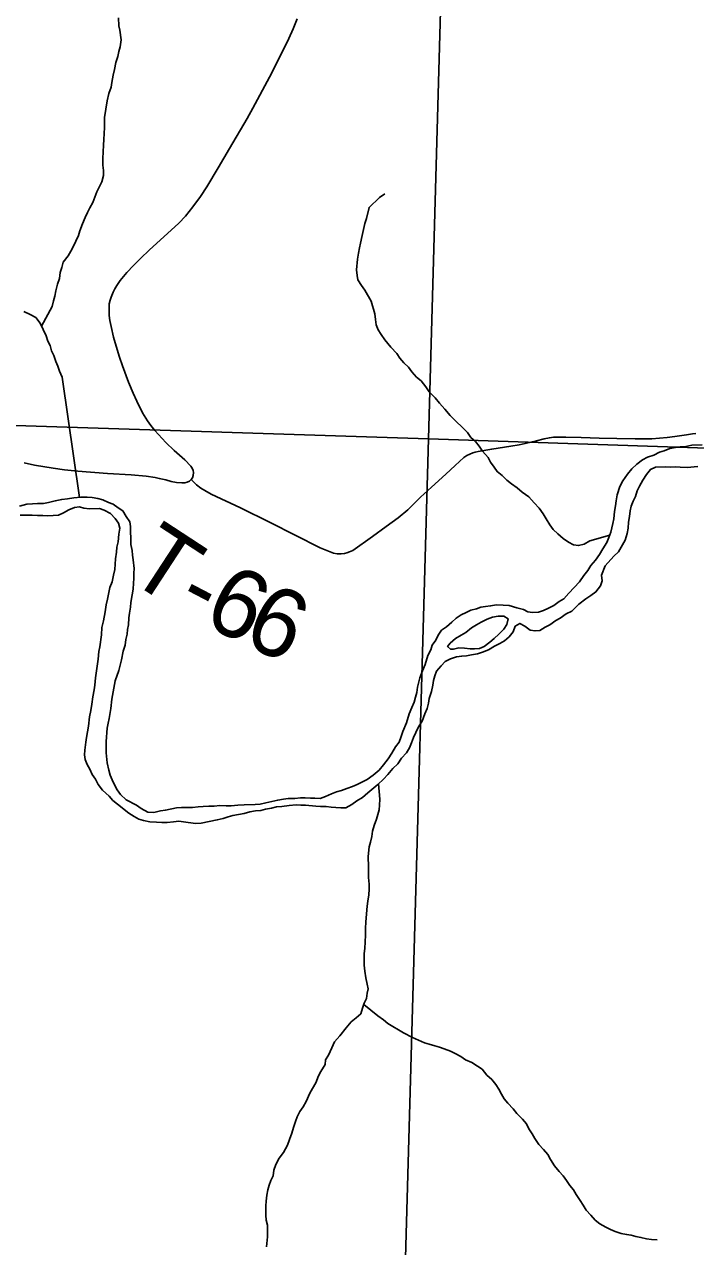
# Model space of a CAD drawing. Extents: x -7.9 to 76.1, y 0 to 22.
# Drawn here: x 7.895 to 8.447, y 14.511 to 15.518 of the extents above; entities that cross this region are included whole.
import ezdxf

# ---------------------------------------------------------------- set-up
doc = ezdxf.new("R2010")
doc.units = 0
for name, color, linetype in [('GM_X_Major_River', 7, 'Continuous'), ('GM_X_Minor_River', 7, 'Continuous'), ('GM_X_Section', 7, 'Continuous'), ('GM_X_State_Route', 7, 'Continuous'), ('GM_X_Township_Road', 7, 'Continuous'), ('GM_X_Township_Road_Text', 7, 'Continuous'), ('SC_Scratch1', 7, 'Continuous')]:
    doc.layers.add(name, color=color, linetype=linetype)

msp = doc.modelspace()

# ---------------------------------------------------------------- linework, layer by layer
at = {"layer": 'GM_X_Major_River'}
for points in [[(8.2669, 15.0364), (8.2707, 15.0376), (8.2745, 15.0384), (8.2786, 15.0388), (8.2835, 15.0397), (8.2889, 15.0393), (8.2938, 15.039), (8.3003, 15.0372), (8.3056, 15.0358), (8.3094, 15.0339), (8.3132, 15.0332), (8.3181, 15.0337), (8.3223, 15.0349), (8.3264, 15.0368), (8.3306, 15.0392), (8.3351, 15.0423), (8.3388, 15.0446), (8.3429, 15.0492), (8.3519, 15.0585), (8.3553, 15.0638), (8.3586, 15.068), (8.3612, 15.0719), (8.3649, 15.0765), (8.3683, 15.0811), (8.3709, 15.0857), (8.3742, 15.091), (8.3761, 15.0952), (8.3775, 15.0994), (8.3793, 15.1067), (8.38, 15.1105), (8.3807, 15.1165), (8.3814, 15.1211), (8.3821, 15.1253), (8.3828, 15.1302), (8.385, 15.1371), (8.3876, 15.1417), (8.3913, 15.1471), (8.395, 15.1517), (8.3991, 15.1555), (8.4037, 15.159), (8.4078, 15.1613), (8.4131, 15.1629), (8.4176, 15.1653), (8.4214, 15.1665), (8.4263, 15.1684), (8.4308, 15.1692), (8.4346, 15.1697), (8.4395, 15.1701), (8.4444, 15.171), (8.4528, 15.1715)], [(8.2317, 14.9774), (8.2328, 14.9813), (8.2342, 14.9851), (8.238, 14.9893), (8.2413, 14.9931), (8.2455, 14.9951), (8.2504, 14.9967), (8.2549, 14.9975), (8.2587, 14.9976), (8.2629, 14.9984), (8.2678, 14.9992), (8.2719, 15.0008), (8.2768, 15.0027), (8.2817, 15.0055), (8.2862, 15.0078), (8.29, 15.0101), (8.2938, 15.0132), (8.2971, 15.0175), (8.2989, 15.022), (8.3027, 15.0244), (8.3069, 15.0221), (8.3111, 15.0188), (8.3153, 15.0181), (8.3191, 15.0185), (8.3236, 15.0212), (8.3274, 15.0232), (8.3323, 15.0267), (8.336, 15.0286), (8.3409, 15.0321), (8.3454, 15.0345), (8.3514, 15.0402), (8.357, 15.0445), (8.3612, 15.0472), (8.3653, 15.0503), (8.369, 15.0553), (8.3705, 15.0595), (8.37, 15.064), (8.373, 15.0717), (8.3801, 15.0797), (8.3838, 15.0832), (8.3894, 15.0928), (8.3912, 15.0985), (8.3919, 15.1027), (8.3922, 15.1076), (8.3929, 15.1125), (8.3936, 15.1171), (8.3943, 15.1209), (8.3961, 15.1251), (8.398, 15.1289), (8.3994, 15.1335), (8.4013, 15.1373), (8.4039, 15.1423), (8.4069, 15.1469), (8.4102, 15.1511), (8.4144, 15.1531), (8.4223, 15.1532), (8.4269, 15.1529), (8.431, 15.1533), (8.4348, 15.153), (8.4405, 15.1527), (8.4492, 15.1536)], [(7.8907, 15.121), (7.8968, 15.1226), (7.9013, 15.1227), (7.9055, 15.1231), (7.9104, 15.1232), (7.9146, 15.124), (7.9202, 15.1252), (7.9255, 15.1265), (7.9301, 15.1269), (7.9354, 15.1277), (7.9411, 15.1282), (7.9464, 15.1283), (7.9505, 15.1279), (7.9551, 15.1273), (7.9593, 15.1262), (7.9639, 15.124), (7.9677, 15.1225), (7.9719, 15.1195), (7.9757, 15.1169), (7.9784, 15.1124), (7.9815, 15.1079), (7.982, 15.1041), (7.982, 15.0992), (7.9825, 15.095), (7.9825, 15.0893), (7.9834, 15.0844), (7.9838, 15.0806), (7.9842, 15.0768), (7.9851, 15.0696), (7.9848, 15.0658), (7.9848, 15.0613), (7.9845, 15.0575), (7.9842, 15.0525)], [(7.8912, 15.1135), (7.8965, 15.1135), (7.9011, 15.1136), (7.9056, 15.1133), (7.9098, 15.1133), (7.914, 15.113), (7.9185, 15.1131), (7.9227, 15.1135), (7.9268, 15.1155), (7.9313, 15.1178), (7.9359, 15.1198), (7.94, 15.1202), (7.9438, 15.1191), (7.9484, 15.1188), (7.9567, 15.1189), (7.9605, 15.1175), (7.9655, 15.1149), (7.9694, 15.1108), (7.9721, 15.107), (7.9733, 15.1028), (7.9726, 15.0979), (7.9719, 15.0914)], [(7.9719, 15.0914), (7.9708, 15.0872), (7.9705, 15.0831), (7.9698, 15.0774), (7.9692, 15.0686), (7.9681, 15.0641), (7.967, 15.0587), (7.9652, 15.0538), (7.9641, 15.0484), (7.9631, 15.0443), (7.962, 15.0397), (7.9613, 15.034), (7.9599, 15.0264), (7.9584, 15.021), (7.9581, 15.015), (7.9568, 15.0051), (7.956, 15.0013), (7.9554, 14.9948), (7.9533, 14.9796), (7.9526, 14.9735), (7.9523, 14.9697), (7.9512, 14.964), (7.9502, 14.9579), (7.9495, 14.9526), (7.9484, 14.9473), (7.9474, 14.9397), (7.946, 14.9305), (7.9453, 14.9267), (7.9446, 14.9199), (7.9443, 14.9161), (7.9447, 14.9123), (7.9463, 14.9082), (7.9486, 14.9044), (7.9506, 14.8999), (7.9533, 14.8961), (7.9556, 14.8916), (7.9591, 14.8871), (7.9645, 14.8822), (7.9676, 14.8785), (7.9714, 14.8755), (7.9806, 14.868), (7.9852, 14.8654), (7.989, 14.8632), (7.9928, 14.8621), (7.9981, 14.8611), (8.0034, 14.8608), (8.008, 14.8605), (8.0122, 14.8605), (8.0175, 14.861), (8.022, 14.8614), (8.0258, 14.8611), (8.0357, 14.8597), (8.0402, 14.8598), (8.0535, 14.8626), (8.0584, 14.8638), (8.0625, 14.865), (8.0663, 14.8662), (8.0709, 14.867), (8.0758, 14.8679), (8.0803, 14.8691), (8.0849, 14.8699), (8.0894, 14.8703), (8.0932, 14.8715), (8.0981, 14.8723), (8.1022, 14.8732), (8.1068, 14.8736), (8.1128, 14.8744), (8.1185, 14.8749), (8.1223, 14.8746), (8.1261, 14.8746), (8.1348, 14.874), (8.1386, 14.8737), (8.1432, 14.8737), (8.1474, 14.873), (8.1512, 14.8727), (8.1553, 14.8724), (8.1595, 14.8724), (8.1644, 14.8752), (8.1685, 14.8783), (8.1731, 14.881), (8.1776, 14.8848), (8.1858, 14.8918), (8.1903, 14.896), (8.194, 14.8999), (8.1981, 14.9049), (8.2023, 14.9087), (8.2052, 14.9133), (8.2093, 14.9179), (8.2119, 14.9218), (8.2134, 14.926), (8.2152, 14.9305), (8.2171, 14.9344), (8.2193, 14.9393), (8.2223, 14.9439), (8.2245, 14.95), (8.2263, 14.9542), (8.2274, 14.9588), (8.2281, 14.9626), (8.2299, 14.9683), (8.231, 14.9736), (8.2317, 14.9774)], [(7.9842, 15.0525), (7.9835, 15.048), (7.9824, 15.0415), (7.9821, 15.0377), (7.9814, 15.0327), (7.9807, 15.0289), (7.9804, 15.0232), (7.9797, 15.0194), (7.9794, 15.0156), (7.9783, 15.0111), (7.9776, 15.0065), (7.9761, 15.0016), (7.9747, 14.9943), (7.9726, 14.9856), (7.9696, 14.9772), (7.9668, 14.962), (7.9658, 14.9544), (7.9644, 14.946), (7.9637, 14.9422), (7.963, 14.938), (7.962, 14.927), (7.962, 14.9232), (7.9621, 14.9179), (7.963, 14.9095), (7.9642, 14.9035), (7.9654, 14.8993), (7.967, 14.8955), (7.9689, 14.8914), (7.9712, 14.8873), (7.9739, 14.8835), (7.9786, 14.879), (7.987, 14.8746), (7.9908, 14.872), (7.9965, 14.869), (8.0014, 14.8687), (8.0067, 14.8699), (8.0109, 14.8707), (8.02, 14.8724), (8.0241, 14.8728), (8.0332, 14.8729), (8.0378, 14.8734), (8.042, 14.8735), (8.0465, 14.8739), (8.051, 14.874), (8.0556, 14.8744), (8.0609, 14.8741), (8.0651, 14.8742), (8.0704, 14.8746), (8.0757, 14.8751), (8.0848, 14.8752), (8.0889, 14.8756), (8.0935, 14.8765), (8.1033, 14.8789), (8.1082, 14.8797), (8.112, 14.8801), (8.1173, 14.8802), (8.1222, 14.8807), (8.126, 14.8807), (8.1302, 14.8804), (8.134, 14.8804), (8.1382, 14.8801), (8.1427, 14.8817), (8.1476, 14.884), (8.1518, 14.8856), (8.1559, 14.8868), (8.1601, 14.8884), (8.165, 14.89), (8.1687, 14.8916), (8.177, 14.8958), (8.1819, 14.8993), (8.1868, 14.9036), (8.1905, 14.9078), (8.1942, 14.9128), (8.1972, 14.9174), (8.2002, 14.9227), (8.2032, 14.9266), (8.205, 14.9311), (8.2064, 14.9353), (8.2094, 14.9426), (8.2116, 14.9498), (8.2138, 14.9552), (8.2156, 14.9594), (8.2167, 14.9636), (8.2178, 14.9674), (8.2185, 14.9719), (8.2203, 14.9796), (8.2225, 14.9853), (8.2247, 14.9906), (8.2268, 14.9979), (8.2294, 15.0025), (8.2305, 15.0063), (8.2335, 15.0105), (8.2353, 15.0147), (8.2383, 15.0189), (8.2424, 15.0216), (8.2466, 15.0255), (8.2503, 15.0286), (8.2545, 15.0313), (8.2586, 15.0332), (8.2624, 15.0352), (8.2669, 15.0364)], [(8.2457, 15.0032), (8.2432, 15.0052), (8.2453, 15.008), (8.2498, 15.0119), (8.2543, 15.0146), (8.2581, 15.0169), (8.2629, 15.0208), (8.2671, 15.0231), (8.2708, 15.0254), (8.2757, 15.0278), (8.2803, 15.0294), (8.2848, 15.0302), (8.2894, 15.0302), (8.2932, 15.028), (8.2921, 15.0235), (8.2895, 15.0196), (8.2854, 15.0154), (8.2816, 15.0119), (8.2779, 15.0088), (8.2734, 15.0054), (8.2696, 15.0038), (8.2654, 15.0033), (8.2617, 15.0033), (8.2571, 15.004), (8.2525, 15.0043), (8.248, 15.0031), (8.2457, 15.0032)]]:
    msp.add_lwpolyline(points, dxfattribs=at)
at = {"layer": 'GM_X_Minor_River'}
for points in [[(7.9721, 15.523), (7.9726, 15.5165), (7.9734, 15.5127), (7.9743, 15.5048), (7.9736, 15.4991), (7.9725, 15.4953), (7.9718, 15.4911), (7.97, 15.4861), (7.9689, 15.4804), (7.9678, 15.4758), (7.9668, 15.4697), (7.9661, 15.4659), (7.9643, 15.4606), (7.9628, 15.4545), (7.9607, 15.4408), (7.9608, 15.4325), (7.9605, 15.4279), (7.9602, 15.4226), (7.9599, 15.4184), (7.9596, 15.4123), (7.9593, 15.4074), (7.9594, 15.4017), (7.9598, 15.3972), (7.9599, 15.393), (7.9584, 15.388), (7.9566, 15.3842), (7.9544, 15.3796), (7.9511, 15.3708), (7.9485, 15.3666), (7.9466, 15.3628), (7.9448, 15.3586), (7.9426, 15.3533), (7.9404, 15.3475), (7.9393, 15.3437), (7.9371, 15.3391), (7.9352, 15.3349), (7.933, 15.3307), (7.9308, 15.3269), (7.9267, 15.3219), (7.9256, 15.3174), (7.9242, 15.3132), (7.9235, 15.3082), (7.922, 15.3036), (7.9206, 15.2983), (7.9199, 15.2937), (7.9188, 15.2899), (7.9177, 15.2854), (7.9089, 15.2691)], [(8.1914, 15.378), (8.1872, 15.3749), (8.1786, 15.3668), (8.1765, 15.3577), (8.175, 15.3535), (8.1729, 15.3436), (8.1714, 15.3375), (8.1707, 15.3337), (8.1697, 15.3291), (8.169, 15.3242), (8.1683, 15.3155), (8.1688, 15.3109), (8.1692, 15.3071), (8.1723, 15.3026), (8.175, 15.2988), (8.1804, 15.2898), (8.1832, 15.2792), (8.1837, 15.2747), (8.1845, 15.2701), (8.1861, 15.266), (8.1884, 15.2622), (8.1915, 15.2577), (8.1965, 15.2517), (8.2015, 15.2465), (8.2038, 15.2427), (8.2073, 15.239), (8.2111, 15.2352), (8.2138, 15.2315), (8.2177, 15.227), (8.2215, 15.224), (8.2254, 15.2191), (8.2281, 15.215), (8.2331, 15.2101), (8.2366, 15.2056), (8.2408, 15.2007), (8.2454, 15.1955), (8.2504, 15.1902), (8.255, 15.1861), (8.2596, 15.1816), (8.2623, 15.1775), (8.2662, 15.1741), (8.2693, 15.1704), (8.272, 15.1662), (8.2766, 15.161), (8.2785, 15.1572), (8.2816, 15.1531), (8.284, 15.1493), (8.2882, 15.146), (8.292, 15.1422), (8.2958, 15.1393), (8.3004, 15.1359), (8.3047, 15.1325), (8.31, 15.1285), (8.3146, 15.1236), (8.3185, 15.1191), (8.322, 15.1146), (8.3243, 15.1104), (8.3274, 15.1055), (8.3301, 15.1018), (8.3339, 15.098), (8.3385, 15.0943), (8.3428, 15.0913), (8.347, 15.0891), (8.3511, 15.0884), (8.3557, 15.0896), (8.3602, 15.0923), (8.3767, 15.0969)], [(7.8943, 15.2812), (7.8996, 15.2787), (7.9042, 15.2761), (7.9077, 15.2716), (7.9127, 15.261), (7.9139, 15.2568), (7.9159, 15.2531), (7.9171, 15.2489)], [(7.9171, 15.2489), (7.919, 15.2448), (7.9206, 15.2399), (7.9222, 15.2361), (7.9237, 15.2319), (7.9257, 15.227), (7.94, 15.1281)], [(8.1862, 14.8922), (8.1875, 14.8797), (8.1872, 14.8747), (8.1868, 14.8709), (8.1847, 14.8633), (8.1828, 14.858), (8.1814, 14.8534), (8.1807, 14.8488), (8.1796, 14.8443), (8.1785, 14.8405), (8.1779, 14.8325), (8.178, 14.8238), (8.1781, 14.815), (8.1786, 14.8097), (8.1786, 14.8055), (8.1783, 14.801), (8.1776, 14.7957), (8.1769, 14.7915), (8.176, 14.7786), (8.1756, 14.7732), (8.1757, 14.7679), (8.1754, 14.7619), (8.1751, 14.7569), (8.1744, 14.7524), (8.1745, 14.7478), (8.1745, 14.7429), (8.175, 14.7379), (8.1758, 14.7326), (8.177, 14.7274), (8.1778, 14.7236), (8.1771, 14.7198), (8.1764, 14.7156), (8.1746, 14.7118), (8.1731, 14.7076), (8.1717, 14.703), (8.1679, 14.6995), (8.1638, 14.6964), (8.1597, 14.6914), (8.1545, 14.6849), (8.15, 14.6799), (8.1478, 14.675), (8.1452, 14.6688), (8.1426, 14.665), (8.1423, 14.6612), (8.1389, 14.6555), (8.1367, 14.6513), (8.1349, 14.6467), (8.1297, 14.6375), (8.1268, 14.6306), (8.1242, 14.6264), (8.1216, 14.6226), (8.1193, 14.618), (8.1179, 14.6142), (8.1164, 14.6092), (8.115, 14.6047), (8.1131, 14.5993), (8.1113, 14.5947), (8.108, 14.5886), (8.1046, 14.584), (8.1017, 14.5787), (8.1002, 14.5741), (8.0995, 14.5695), (8.0977, 14.5657), (8.0962, 14.5619), (8.0951, 14.5581), (8.0944, 14.5535), (8.0937, 14.5486), (8.0934, 14.5448), (8.0935, 14.541), (8.0935, 14.5372), (8.0939, 14.533), (8.0948, 14.5289), (8.0949, 14.5194), (8.0942, 14.511)], [(8.1741, 14.7105), (8.1857, 14.7013), (8.1903, 14.6979), (8.1941, 14.695), (8.2068, 14.6872), (8.2144, 14.6835), (8.2243, 14.6791), (8.2281, 14.678), (8.2327, 14.6765), (8.2365, 14.6754), (8.2403, 14.674), (8.2456, 14.6722), (8.2495, 14.6703), (8.254, 14.6677), (8.2579, 14.6651), (8.2632, 14.6629), (8.2678, 14.6599), (8.2716, 14.6573), (8.2755, 14.6525), (8.2797, 14.6487), (8.2828, 14.6446), (8.2855, 14.6408), (8.2875, 14.6367), (8.2898, 14.6329), (8.2929, 14.6292), (8.2971, 14.6247), (8.3002, 14.6209), (8.3048, 14.6161), (8.3083, 14.6123), (8.3102, 14.6082), (8.3129, 14.604), (8.3149, 14.6003), (8.3183, 14.5954), (8.3222, 14.5913), (8.3257, 14.5871), (8.328, 14.583), (8.3311, 14.5777), (8.335, 14.5732), (8.3384, 14.5695), (8.3411, 14.5657), (8.3438, 14.5616), (8.3469, 14.5579), (8.3492, 14.5541), (8.3523, 14.5492), (8.3547, 14.5454), (8.3574, 14.5413), (8.3612, 14.5372), (8.3647, 14.5331), (8.3685, 14.5301), (8.3735, 14.5271), (8.3773, 14.5253), (8.3811, 14.5238), (8.3861, 14.522), (8.3906, 14.5213), (8.3944, 14.5206), (8.3982, 14.5195), (8.4024, 14.5188), (8.407, 14.5177), (8.4112, 14.517), (8.4157, 14.5167)]]:
    msp.add_lwpolyline(points, dxfattribs=at)
at = {"layer": 'GM_X_Section'}
for points in [[(8.2558, 16.1845), (8.2275, 15.1763), (7.1984, 15.2096), (7.2312, 16.2186)], [(7.1984, 15.2096), (8.2275, 15.1763), (8.1994, 14.1795), (7.1768, 14.2053)]]:
    msp.add_lwpolyline(points, close=True, dxfattribs=at)
at = {"layer": 'GM_X_State_Route'}
msp.add_lwpolyline([(7.8946, 15.1565), (7.9031, 15.1547), (7.9185, 15.1521), (7.9278, 15.1508), (7.9386, 15.1497), (7.9632, 15.1477), (7.9827, 15.1466), (7.9949, 15.1457), (8.0024, 15.1444), (8.0057, 15.1437), (8.0111, 15.1425), (8.0157, 15.1412), (8.02, 15.1404), (8.0243, 15.14), (8.0267, 15.1402), (8.0288, 15.1406), (8.0306, 15.1414), (8.0321, 15.1427), (8.0331, 15.1441), (8.0338, 15.1462), (8.0341, 15.1485), (8.0338, 15.1502), (8.033, 15.1522), (8.0319, 15.1537), (8.0268, 15.1589), (8.0181, 15.1668), (8.0111, 15.1734), (8.002, 15.1831), (7.9988, 15.1873), (7.996, 15.1912), (7.9919, 15.1978), (7.9872, 15.2074), (7.9842, 15.2139), (7.9805, 15.2229), (7.9755, 15.2365), (7.9729, 15.2435), (7.971, 15.2499), (7.9682, 15.2599), (7.9661, 15.2688), (7.9651, 15.2737), (7.9646, 15.2779), (7.9644, 15.2811), (7.9646, 15.2875), (7.9653, 15.2904), (7.9661, 15.293), (7.9678, 15.2972), (7.9691, 15.2998), (7.9708, 15.3026), (7.9737, 15.3066), (7.9791, 15.3132), (7.9845, 15.3189), (7.9905, 15.3251), (7.9974, 15.3316), (8.0218, 15.3538), (8.0275, 15.3597), (8.0335, 15.3673), (8.0396, 15.3758), (8.0449, 15.3839), (8.0544, 15.3994), (8.0635, 15.4153), (8.0781, 15.4401), (8.0829, 15.4486), (8.0965, 15.4742), (8.1092, 15.4991), (8.1125, 15.5058), (8.116, 15.5139), (8.1194, 15.5222)], dxfattribs=at)
at = {"layer": 'GM_X_Township_Road'}
msp.add_lwpolyline([(8.0321, 15.1427), (8.0364, 15.1385), (8.0401, 15.1357), (8.0432, 15.1337), (8.0484, 15.1308), (8.0728, 15.1196), (8.097, 15.1073), (8.1383, 15.0867), (8.1437, 15.0844), (8.1493, 15.0823), (8.1524, 15.0817), (8.1556, 15.0816), (8.1584, 15.0819), (8.1601, 15.0824), (8.1624, 15.0832), (8.1651, 15.0845), (8.1815, 15.096), (8.1927, 15.1041), (8.2026, 15.1112), (8.2105, 15.1179), (8.221, 15.1283), (8.2299, 15.1365), (8.2417, 15.1473), (8.2493, 15.1543), (8.2567, 15.1609), (8.2591, 15.1626), (8.2614, 15.1638), (8.264, 15.1648), (8.2658, 15.1654), (8.2685, 15.166), (8.2795, 15.1679), (8.2952, 15.1702), (8.302, 15.1713), (8.307, 15.1724), (8.3163, 15.1748), (8.3227, 15.1763), (8.327, 15.1772), (8.3303, 15.1777), (8.3337, 15.1778), (8.3405, 15.1778), (8.3532, 15.1773), (8.368, 15.177), (8.3826, 15.1766), (8.3976, 15.1762), (8.4113, 15.1764), (8.4176, 15.1769), (8.424, 15.1775), (8.4304, 15.1783), (8.44, 15.1796), (8.4448, 15.1803), (8.4476, 15.1808)], dxfattribs=at)
at = {"layer": 'SC_Scratch1'}
for points in [[(8.9, 15.1537), (8.9, 16.161), (8.2558, 16.1845), (8.2275, 15.1763)], [(8.9, 14.1574), (8.9, 15.1537), (8.2275, 15.1763), (8.1994, 14.1795)]]:
    msp.add_lwpolyline(points, close=True, dxfattribs=at)

# ---------------------------------------------------------------- texts
at = {"layer": 'GM_X_Township_Road_Text'}
for s, rotation, p in [('T', 326.8389, (7.9771, 15.0624)), ('6', 333.7237, (8.0399, 15.0247)), ('-', 332.4198, (8.0179, 15.0361)), ('6', 335.1192, (8.0726, 15.0085))]:
    msp.add_text(s, height=0.0568, rotation=rotation, dxfattribs=at).set_placement(p)

doc.saveas('drawing.dxf')
